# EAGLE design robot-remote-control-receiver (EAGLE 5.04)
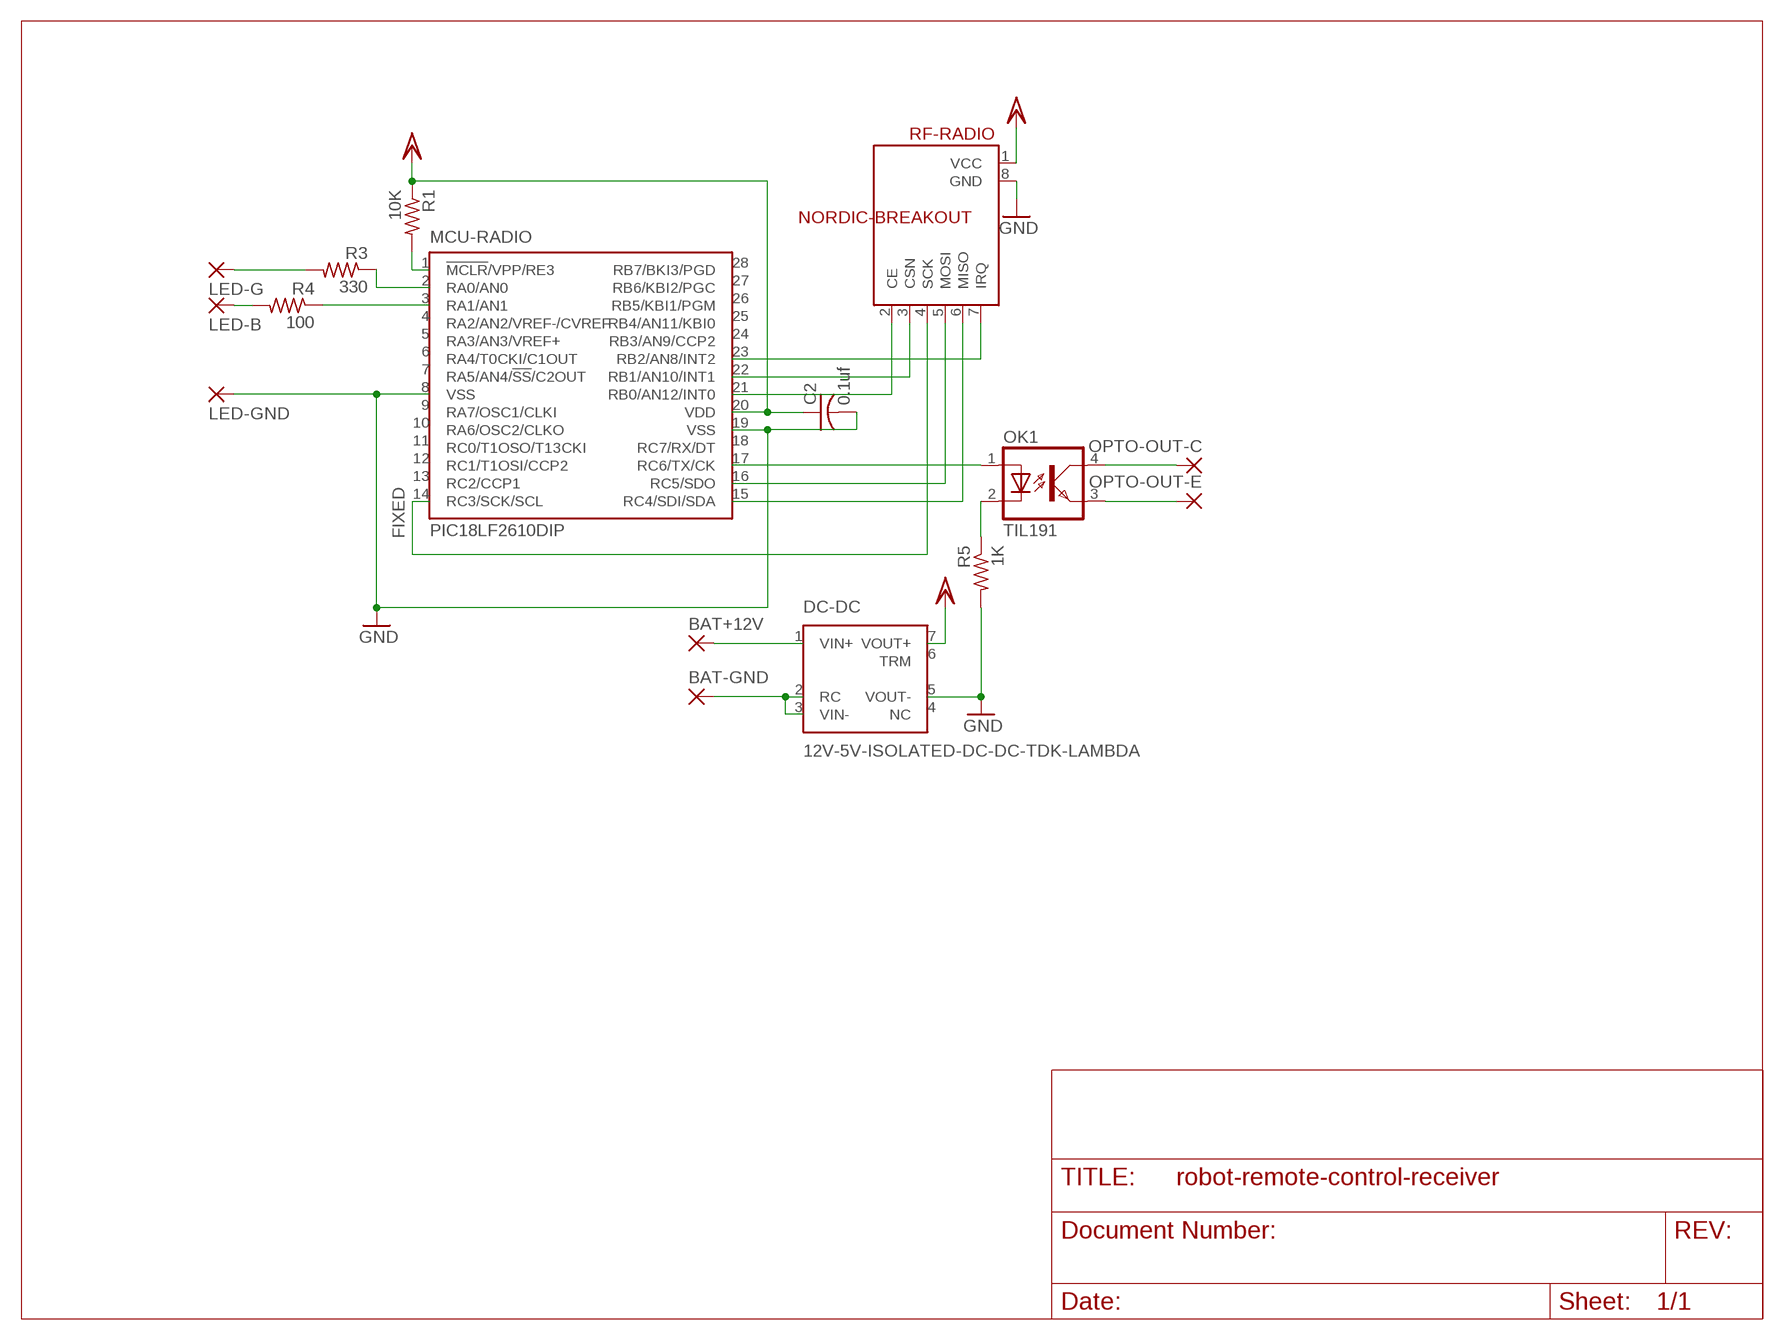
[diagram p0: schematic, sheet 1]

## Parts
BAT+12V  2,54/0,8  [2,54/0,8]
BAT-GND  2,54/0,8  [2,54/0,8]
C2  0.1uf  C-US050-024X044  [C050-024X044]
DC-DC  12V-5V-ISOLATED-DC-DC-TDK-LAMBDA  [DC-DC-12-5-TDK-LAMBDA]
LED-B  WIREPAD2,15/1,0  [2,15/1,0]
LED-G  WIREPAD2,15/1,0  [2,15/1,0]
LED-GND  WIREPAD2,15/1,0  [2,15/1,0]
MCU-RADIO  PIC18LF2610DIP  [DIL28-3]
OK1  TIL191  [DIL04]
OPTO-OUT-C  WIREPAD2,15/1,0  [2,15/1,0]
OPTO-OUT-E  WIREPAD2,15/1,0  [2,15/1,0]
R1  10K  R-US_0204/7  [0204/7]
R3  330  R-US_0204/7  [0204/7]
R4  100  R-US_0204/7  [0204/7]
R5  1K  R-US_0204/7  [0204/7]
RF-RADIO  NORDIC-BREAKOUT  [8SIL]

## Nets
GND2: C2.2 DC-DC.5(VOUT-) LED-GND.1(P) MCU-RADIO.8(VSS) MCU-RADIO.19(VSS) R5.2 RF-RADIO.8(GND) ; supply symbol labelled GND
N$1: LED-B.1(P) R4.2
N$2: MCU-RADIO.2(RA0/AN0) R3.1
N$3: OK1.2(C) R5.1
N$4: MCU-RADIO.17(RC6/TX/CK) OK1.1(A)
N$5: MCU-RADIO.15(RC4/SDI/SDA) RF-RADIO.6(MISO)
N$6: MCU-RADIO.16(RC5/SDO) RF-RADIO.5(MOSI)
N$7: MCU-RADIO.14(RC3/SCK/SCL) RF-RADIO.4(SCK)
N$10: MCU-RADIO.1(!MCLR!/VPP/RE3) R1.2
N$11: MCU-RADIO.22(RB1/AN10/INT1) RF-RADIO.3(CSN)
N$12: MCU-RADIO.23(RB2/AN8/INT2) RF-RADIO.7(IRQ)
N$13: MCU-RADIO.21(RB0/AN12/INT0) RF-RADIO.2(CE)
N$14: LED-G.1(P) R3.2
N$15: MCU-RADIO.3(RA1/AN1) R4.1
N$16: BAT-GND.1(P) DC-DC.2(RC) DC-DC.3(VIN-)
N$17: BAT+12V.1(P) DC-DC.1(VIN+)
N$18: OK1.3(EMIT) OPTO-OUT-E.1(P)
N$19: OK1.4(COL) OPTO-OUT-C.1(P)
VCC2: C2.1 DC-DC.7(VOUT+) MCU-RADIO.20(VDD) R1.1 RF-RADIO.1(VCC)
Unconnected: DC-DC.4(NC) DC-DC.6(TRM) MCU-RADIO.4(RA2/AN2/VREF-/CVREF) MCU-RADIO.5(RA3/AN3/VREF+) MCU-RADIO.6(RA4/T0CKI/C1OUT) MCU-RADIO.7(RA5/AN4/!SS!/C2OUT) MCU-RADIO.9(RA7/OSC1/CLKI) MCU-RADIO.10(RA6/OSC2/CLKO) MCU-RADIO.11(RC0/T1OSO/T13CKI) MCU-RADIO.12(RC1/T1OSI/CCP2) MCU-RADIO.13(RC2/CCP1) MCU-RADIO.18(RC7/RX/DT) MCU-RADIO.24(RB3/AN9/CCP2) MCU-RADIO.25(RB4/AN11/KBI0) MCU-RADIO.26(RB5/KBI1/PGM) MCU-RADIO.27(RB6/KBI2/PGC) MCU-RADIO.28(RB7/BKI3/PGD)

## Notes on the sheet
- FIXED

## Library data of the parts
BAT+12V BAT-GND = wirepad:2,54/0,8: THROUGH-HOLE PAD
C2 = rcl:C-US: CAPACITOR, American symbol
DC-DC = trl:12V-5V-ISOLATED-DC-DC-TDK-LAMBDA
LED-B LED-G LED-GND OPTO-OUT-C OPTO-OUT-E = wirepad:WIREPAD: Wire PAD connect wire on PCB
MCU-RADIO = trl:PIC18LF2610: PIC18LF2610 28-Pin, No USB or EEPROM
OK1 = optocoupler:TIL191: TEXAS INSTRUMENTS OPTO COUPLER
R1 R3-R5 = resistor:R-US_: RESISTOR, American symbol
RF-RADIO = trl:NORDIC-BREAKOUT: Spark Fun Electronic's Nordic Semiconductor nRF24L01 with chip antenna

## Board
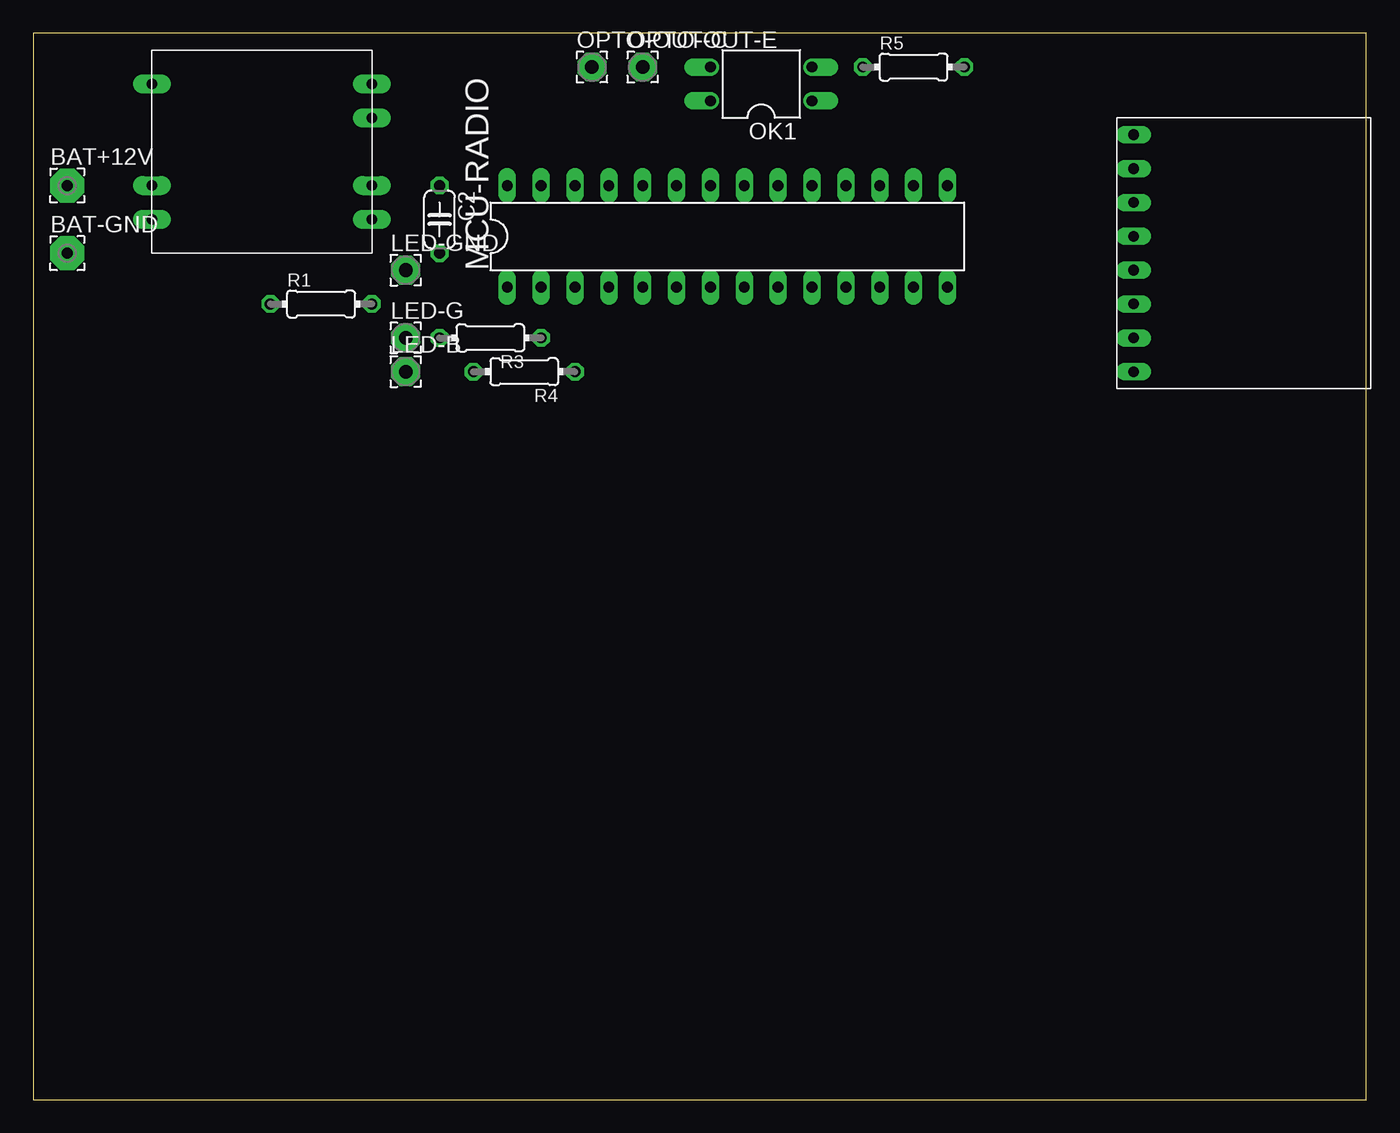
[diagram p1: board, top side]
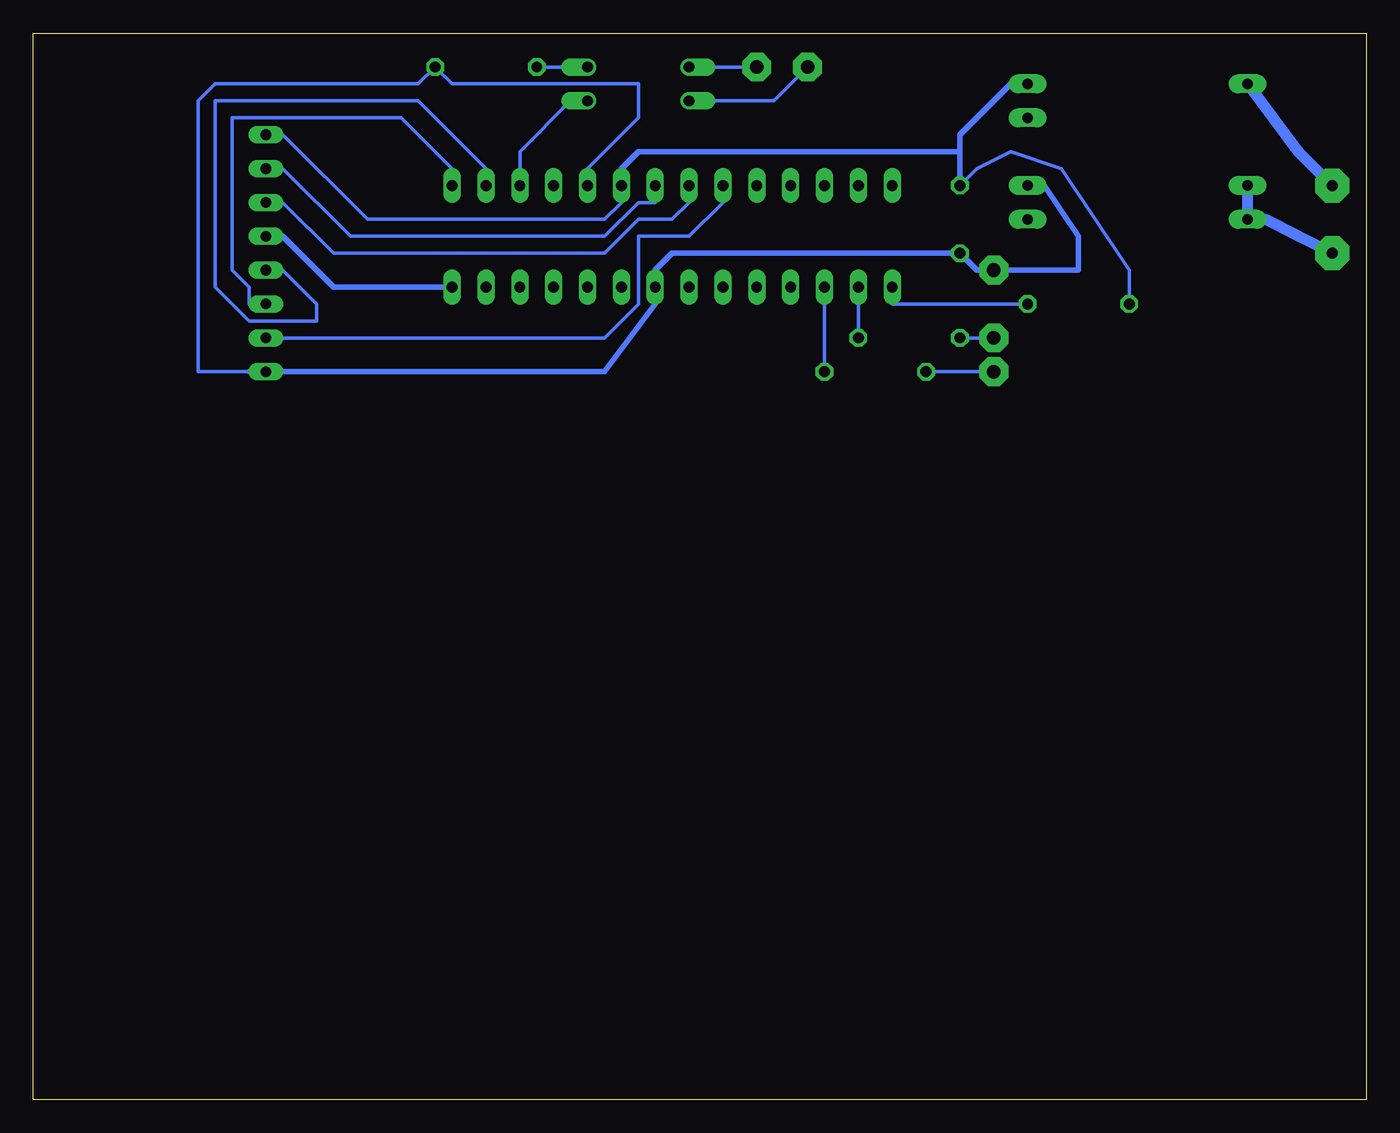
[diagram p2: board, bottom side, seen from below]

Size 100 x 80 mm. Coordinates in mm from the lower left corner, seen from the top.
Outline: 0,0 100,0 100,80 0,80 0,0
Copper layers (1*16): Top 0.035mm / dielectric 1.5mm / Bottom 0.035mm
Design rules "default": minimum track width 10mil, minimum drill 24mil, track to track 8mil, track to pad 8mil, pad to pad 8mil, via to via 8mil, smd to smd 8mil, copper to edge 40mil, drill to drill 8mil, minimum pad ring 10mil, minimum via ring 8mil, stop-mask expansion 4mil, vias tented up to drill 0mil, thermal gap 10mil

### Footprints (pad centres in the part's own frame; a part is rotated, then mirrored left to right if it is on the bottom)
2,54/0,8 = drill 0.813 pad 2.54 octagon: 1 0,0
C050-024X044 = drill 0.813 octagon: 1 -2.54,0; 2 2.54,0
DC-DC-12-5-TDK-LAMBDA = drill 0.8 pad 1.422 long: 1 -8.89,5.08; 2 -8.89,-2.54; 3 -8.89,-5.08; 4 7.62,-5.08; 5 7.62,-2.54; 6 7.62,2.54; 7 7.62,5.08
2,15/1,0 = drill 1.016 pad 2.159 octagon: 1 0,0
DIL28-3 = drill 0.813 long: 1 -16.51,-3.81; 2 -13.97,-3.81; 3 -11.43,-3.81; 4 -8.89,-3.81; 5 -6.35,-3.81; 6 -3.81,-3.81; 7 -1.27,-3.81; 8 1.27,-3.81; 9 3.81,-3.81; 10 6.35,-3.81; 11 8.89,-3.81; 12 11.43,-3.81; 13 13.97,-3.81; 14 16.51,-3.81; 15 16.51,3.81; 16 13.97,3.81; 17 11.43,3.81; 18 8.89,3.81; 19 6.35,3.81; 20 3.81,3.81; 21 1.27,3.81; 22 -1.27,3.81; 23 -3.81,3.81; 24 -6.35,3.81; 25 -8.89,3.81; 26 -11.43,3.81; 27 -13.97,3.81; 28 -16.51,3.81
DIL04 = drill 0.813 offset: 1 -1.27,-3.81; 2 1.27,-3.81; 3 1.27,3.81; 4 -1.27,3.81
0204/7 = drill 0.813 octagon: 1 -3.81,0; 2 3.81,0
8SIL = drill 0.8 long: 1 -8.89,-8.89; 2 -6.35,-8.89; 3 -3.81,-8.89; 4 -1.27,-8.89; 5 1.27,-8.89; 6 3.81,-8.89; 7 6.35,-8.89; 8 8.89,-8.89

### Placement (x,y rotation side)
BAT+12V  2.54,68.58 0 top
BAT-GND  2.54,63.5 0 top
C2  30.48,66.04 270 top
DC-DC  17.78,71.12 0 top
LED-B  27.94,54.61 0 top
LED-G  27.94,57.15 0 top
LED-GND  27.94,62.23 0 top
MCU-RADIO  52.07,64.77 0 top
OK1  54.61,76.2 90 top
OPTO-OUT-C  41.91,77.47 0 top
OPTO-OUT-E  45.72,77.47 0 top
R1  21.59,59.69 0 top
R3  34.29,57.15 180 top
R4  36.83,54.61 180 top
R5  66.04,77.47 0 top
RF-RADIO  91.44,63.5 270 top

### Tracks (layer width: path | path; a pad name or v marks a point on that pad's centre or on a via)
GND2
  Bottom 0.254: MCU-RADIO.19 58.42,69.85 54.61,73.66 54.61,76.2 68.58,76.2 R5.2 71.12,76.2 86.36,76.2 87.63,74.93 87.63,54.61 83.82,54.61
  Bottom 0.406: 24.13,62.23 21.59,62.23 21.59,63.5 21.59,64.77 24.13,68.58 DC-DC.5 | 24.13,62.23 26.67,62.23 24.13,62.23 | 24.13,62.23 LED-GND.1 29.21,62.23 C2.2 52.07,63.5 53.34,62.23 MCU-RADIO.8 53.34,59.69 57.15,54.61 81.28,54.61 RF-RADIO.8 83.82,54.61
N$1
  Bottom 0.254: LED-B.1 R4.2
N$2
  Bottom 0.254: R3.1 38.1,59.69 MCU-RADIO.2
N$3
  Bottom 0.254: R5.1 59.69,77.47 OK1.2
N$4
  Bottom 0.254: OK1.1 59.69,74.93 63.5,71.12 63.5,69.85 MCU-RADIO.17
N$5
  Bottom 0.254: RF-RADIO.6 83.82,59.69 83.82,60.96 85.09,62.23 85.09,73.66 72.39,73.66 68.58,69.85 MCU-RADIO.15
N$6
  Bottom 0.254: RF-RADIO.5 81.28,62.23 78.74,59.69 78.74,58.42 83.82,58.42 86.36,60.96 86.36,74.93 71.12,74.93 66.04,69.85 MCU-RADIO.16
N$7
  Bottom 0.254: RF-RADIO.4 81.28,64.77
  Bottom 0.406: MCU-RADIO.14 77.47,60.96 78.74,62.23 81.28,64.77
N$10
  Bottom 0.254: R1.2 26.67,59.69 35.56,59.69 MCU-RADIO.1
N$11
  Bottom 0.254: RF-RADIO.3 81.28,67.31 77.47,63.5 57.15,63.5 54.61,66.04 52.07,66.04 50.8,67.31 MCU-RADIO.22
N$12
  Bottom 0.254: RF-RADIO.7 81.28,57.15 57.15,57.15 54.61,59.69 54.61,64.77 50.8,64.77 48.26,67.31 MCU-RADIO.23
N$13
  Bottom 0.254: RF-RADIO.2 81.28,69.85 76.2,64.77 57.15,64.77 54.61,67.31 53.34,67.31 MCU-RADIO.21
N$14
  Bottom 0.254: LED-G.1 R3.2
N$15
  Bottom 0.254: R4.1 40.64,59.69 MCU-RADIO.3
N$16
  Bottom 0.813: DC-DC.2 DC-DC.3 7.62,66.04 5.08,64.77 BAT-GND.1
N$17
  Bottom 0.813: BAT+12V.1 5.08,71.12 DC-DC.1
N$18
  Bottom 0.254: OPTO-OUT-E.1 49.53,77.47 OK1.3
N$19
  Bottom 0.254: OPTO-OUT-C.1 44.45,74.93 49.53,74.93 OK1.4
VCC2
  Bottom 0.254: R1.1 17.78,62.23 22.86,69.85 26.67,71.12 29.21,69.85 C2.1 | RF-RADIO.1 81.28,72.39 74.93,66.04 57.15,66.04 55.88,67.31 MCU-RADIO.20
  Bottom 0.406: C2.1 30.48,71.12 | 30.48,71.12 30.48,72.39 26.67,76.2 DC-DC.7 | 30.48,71.12 54.61,71.12 55.88,69.85 MCU-RADIO.20

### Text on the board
Document: FIXED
